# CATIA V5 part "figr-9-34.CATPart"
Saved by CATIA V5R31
Part number: Part1
Bounding box of the stored display mesh (mm): x -250 to 0, y -60 to 60, z 0 to 100
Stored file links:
  D:\PROJECTS\Project 2021\US EDITION\CATIA V5 6R 2021\Resources\Part Files\c09_catia_v5_6r2021_prt\c09_catia_v5_6r2021_prt\figr-9-34.CATPart
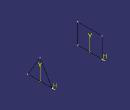
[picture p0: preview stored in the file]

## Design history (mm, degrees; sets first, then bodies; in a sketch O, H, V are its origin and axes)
Body1 (main body)
  Sketch1 on yz-plane, origin (0, 0, 0), H (0, 1, 0), V (0, 0, 1)
    point P1 (-60, 0)
    line L1 (-60, 0) -> (0, 100)
    point P2 (0, 100)
    line L2 (0, 100) -> (60, 0)
    point P3 (60, 0)
    line L3 (60, 0) -> (-60, 0)
    coincidence: P1 H, P2 V, P3 H
    horizontal: L3 H
    midpoint: O L3
  Sketch2, origin (-250, 0, 0), H (0, 1, 0), V (0, 0, 1)
    point P1 (-60, 0)
    line L1 (-60, 0) -> (60, 0)
    line L2 (60, 0) -> (60, 100)
    line L3 (60, 100) -> (-60, 100)
    line L4 (-60, 100) -> (-60, 0)
    coincidence: P1 H
    horizontal: L1 H, L3 H
    vertical: L2 V, L4 V
  Loft1: Sections (Sketch1; Sketch2), SectionCouplingPoints ({coupling CouplingPoints (vertex [element of Sketch1 | element of Sketch1]; vertex [element of Sketch2 | element of Sketch2])}; {coupling CouplingPoints (vertex [element of Sketch1 | element of Sketch1]; vertex [element of Sketch2 | element of Sketch2])}; {coupling CouplingPoints (vertex [element of Sketch1 | element of Sketch1]; vertex [element of Sketch2 | element of Sketch2])})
